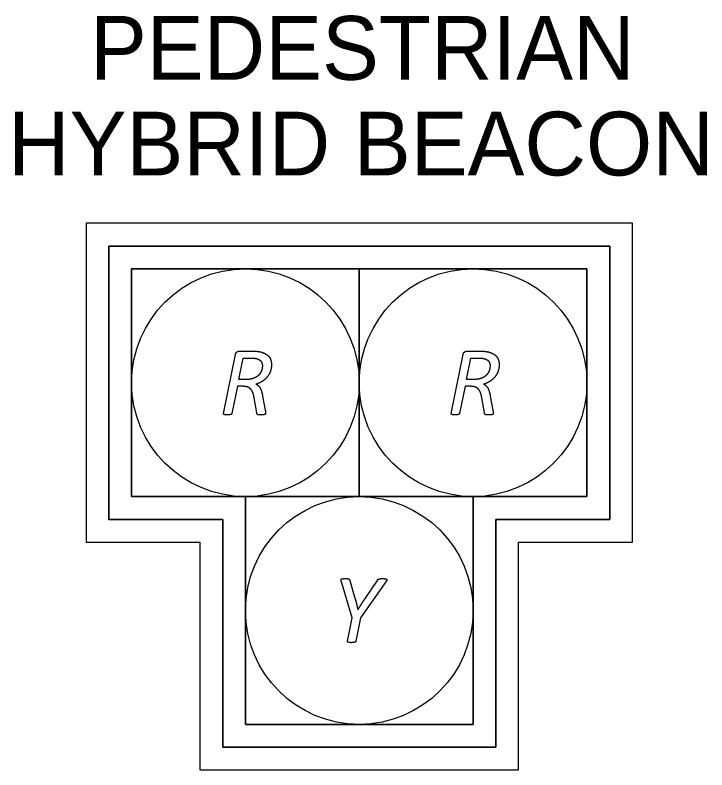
# Model space of a CAD drawing. Extents: x -30.3 to 21.6, y 6.6 to 27.2.
# Drawn here: x 16.72 to 18.239, y 9.926 to 11.583 of the extents above; entities that cross this region are included whole.
import ezdxf

# ---------------------------------------------------------------- set-up
doc = ezdxf.new("R2010")
doc.units = 0
doc.layers.add('UT_X_Water', color=7, linetype='Continuous')
doc.layers.add('VG_X_Cells', color=7, linetype='Continuous')

msp = doc.modelspace()

# ---------------------------------------------------------------- linework, layer by layer
at = {"layer": 'VG_X_Cells'}
for p, q in [((17.2127, 10.8455), (17.243, 10.8455)), ((17.2127, 10.8455), (17.243, 10.8455)), ((17.7127, 10.8455), (17.743, 10.8455)), ((17.7127, 10.8455), (17.743, 10.8455)), ((17.1778, 10.7088), (17.2037, 10.838)), ((17.1778, 10.7088), (17.2037, 10.838)), ((17.6778, 10.7088), (17.7037, 10.838)), ((17.6778, 10.7088), (17.7037, 10.838)), ((17.2631, 10.8135), (17.2631, 10.8135)), ((17.7631, 10.8135), (17.7631, 10.8135)), ((17.2506, 10.71), (17.2451, 10.7428)), ((17.2506, 10.71), (17.2451, 10.7428)), ((17.2637, 10.747), (17.2695, 10.7162)), ((17.2637, 10.747), (17.2695, 10.7162)), ((17.7506, 10.71), (17.7451, 10.7428)), ((17.7506, 10.71), (17.7451, 10.7428)), ((17.7637, 10.747), (17.7695, 10.7162)), ((17.7637, 10.747), (17.7695, 10.7162)), ((17.4553, 10.3417), (17.4664, 10.3035)), ((17.4553, 10.3417), (17.4664, 10.3035)), ((17.4893, 10.3034), (17.5156, 10.3423)), ((17.4893, 10.3034), (17.5156, 10.3423)), ((17.4728, 10.2778), (17.473, 10.2778)), ((17.4728, 10.2778), (17.473, 10.2778))]:
    msp.add_line(p, q, dxfattribs=at)
for points in [[(18.0759, 10.4262), (18.0759, 11.1262), (16.8759, 11.1262), (16.8759, 10.4262), (17.1259, 10.4262), (17.1259, 9.9262), (17.8259, 9.9262), (17.8259, 10.4262)], [(17.7759, 10.4762), (17.7759, 9.9762), (17.1759, 9.9762), (17.1759, 10.4762), (16.9259, 10.4762), (16.9259, 11.0762), (18.0259, 11.0762), (18.0259, 10.4762)], [(18.0259, 10.4762), (18.0259, 11.0762), (16.9259, 11.0762), (16.9259, 10.4762), (17.1759, 10.4762), (17.1759, 9.9762), (17.7759, 9.9762), (17.7759, 10.4762)], [(17.7259, 10.5262), (17.7259, 10.0262), (17.2259, 10.0262), (17.2259, 10.5262), (16.9759, 10.5262), (16.9759, 11.0262), (17.9759, 11.0262), (17.9759, 10.5262)], [(16.9759, 10.5262), (17.4759, 10.5262), (17.4759, 11.0262), (16.9759, 11.0262)], [(17.4759, 10.5262), (17.9759, 10.5262), (17.9759, 11.0262), (17.4759, 11.0262)], [(17.2259, 10.0262), (17.7259, 10.0262), (17.7259, 10.5262), (17.2259, 10.5262)]]:
    msp.add_lwpolyline(points, close=True, dxfattribs=at)
for points in [[(17.2276, 10.7833), (17.2113, 10.7833), (17.2207, 10.8303), (17.2399, 10.8303)], [(17.7276, 10.7833), (17.7113, 10.7833), (17.7207, 10.8303), (17.7399, 10.8303)], [(17.2206, 10.7683), (17.2082, 10.7683), (17.1963, 10.7088)], [(17.2206, 10.7683), (17.2082, 10.7683), (17.1963, 10.7088)], [(17.7206, 10.7683), (17.7082, 10.7683), (17.6963, 10.7088)], [(17.7206, 10.7683), (17.7082, 10.7683), (17.6963, 10.7088)], [(17.4501, 10.2088), (17.4604, 10.2603), (17.4366, 10.3389)], [(17.4501, 10.2088), (17.4604, 10.2603), (17.4366, 10.3389)], [(17.5341, 10.3389), (17.4789, 10.2603), (17.4687, 10.2088)], [(17.5341, 10.3389), (17.4789, 10.2603), (17.4687, 10.2088)]]:
    msp.add_lwpolyline(points, dxfattribs=at)
for centre in [(17.2259, 10.7762), (17.7259, 10.7762), (17.4759, 10.2762)]:
    msp.add_circle(centre, 0.25, dxfattribs=at)
for points in [[(17.2037, 10.838), (17.2045, 10.8422), (17.2071, 10.8438)], [(17.2037, 10.838), (17.2045, 10.8422), (17.2071, 10.8438)], [(17.2071, 10.8438), (17.2096, 10.8455), (17.2127, 10.8455)], [(17.2071, 10.8438), (17.2096, 10.8455), (17.2127, 10.8455)], [(17.243, 10.8455), (17.2529, 10.8455), (17.2604, 10.8436)], [(17.243, 10.8455), (17.2529, 10.8455), (17.2604, 10.8436)], [(17.2604, 10.8436), (17.2679, 10.8416), (17.2729, 10.8379)], [(17.2604, 10.8436), (17.2679, 10.8416), (17.2729, 10.8379)], [(17.7037, 10.838), (17.7045, 10.8422), (17.7071, 10.8438)], [(17.7037, 10.838), (17.7045, 10.8422), (17.7071, 10.8438)], [(17.7071, 10.8438), (17.7096, 10.8455), (17.7127, 10.8455)], [(17.7071, 10.8438), (17.7096, 10.8455), (17.7127, 10.8455)], [(17.743, 10.8455), (17.7529, 10.8455), (17.7604, 10.8436)], [(17.743, 10.8455), (17.7529, 10.8455), (17.7604, 10.8436)], [(17.7604, 10.8436), (17.7679, 10.8416), (17.7729, 10.8379)], [(17.7604, 10.8436), (17.7679, 10.8416), (17.7729, 10.8379)], [(17.2399, 10.8303), (17.2461, 10.8303), (17.2505, 10.8291)], [(17.2505, 10.8291), (17.255, 10.8279), (17.2578, 10.8256)], [(17.2578, 10.8256), (17.2605, 10.8234), (17.2618, 10.8202)], [(17.2729, 10.8379), (17.278, 10.8342), (17.2805, 10.8288)], [(17.2729, 10.8379), (17.278, 10.8342), (17.2805, 10.8288)], [(17.2805, 10.8288), (17.2831, 10.8233), (17.2831, 10.8163)], [(17.2805, 10.8288), (17.2831, 10.8233), (17.2831, 10.8163)], [(17.7399, 10.8303), (17.7461, 10.8303), (17.7505, 10.8291)], [(17.7505, 10.8291), (17.755, 10.8279), (17.7578, 10.8256)], [(17.7578, 10.8256), (17.7605, 10.8234), (17.7618, 10.8202)], [(17.7729, 10.8379), (17.778, 10.8342), (17.7805, 10.8288)], [(17.7729, 10.8379), (17.778, 10.8342), (17.7805, 10.8288)], [(17.7805, 10.8288), (17.7831, 10.8233), (17.7831, 10.8163)], [(17.7805, 10.8288), (17.7831, 10.8233), (17.7831, 10.8163)], [(17.2631, 10.8135), (17.2631, 10.8078), (17.2611, 10.8024)], [(17.2618, 10.8202), (17.2631, 10.8171), (17.2631, 10.8135)], [(17.2831, 10.8163), (17.2831, 10.8089), (17.281, 10.8022)], [(17.2831, 10.8163), (17.2831, 10.8089), (17.281, 10.8022)], [(17.7631, 10.8135), (17.7631, 10.8078), (17.7611, 10.8024)], [(17.7618, 10.8202), (17.7631, 10.8171), (17.7631, 10.8135)], [(17.7831, 10.8163), (17.7831, 10.8089), (17.781, 10.8022)], [(17.7831, 10.8163), (17.7831, 10.8089), (17.781, 10.8022)], [(17.2549, 10.7927), (17.2506, 10.7885), (17.2439, 10.7859)], [(17.2611, 10.8024), (17.2591, 10.797), (17.2549, 10.7927)], [(17.2746, 10.79), (17.2704, 10.7844), (17.264, 10.78)], [(17.2746, 10.79), (17.2704, 10.7844), (17.264, 10.78)], [(17.281, 10.8022), (17.2789, 10.7956), (17.2746, 10.79)], [(17.281, 10.8022), (17.2789, 10.7956), (17.2746, 10.79)], [(17.7549, 10.7927), (17.7506, 10.7885), (17.7439, 10.7859)], [(17.7611, 10.8024), (17.7591, 10.797), (17.7549, 10.7927)], [(17.7746, 10.79), (17.7704, 10.7844), (17.764, 10.78)], [(17.7746, 10.79), (17.7704, 10.7844), (17.764, 10.78)], [(17.781, 10.8022), (17.7789, 10.7956), (17.7746, 10.79)], [(17.781, 10.8022), (17.7789, 10.7956), (17.7746, 10.79)], [(17.2439, 10.7859), (17.2372, 10.7833), (17.2276, 10.7833)], [(17.264, 10.78), (17.2575, 10.7757), (17.249, 10.773)], [(17.264, 10.78), (17.2575, 10.7757), (17.249, 10.773)], [(17.249, 10.773), (17.2547, 10.7709), (17.2583, 10.7644)], [(17.249, 10.773), (17.2547, 10.7709), (17.2583, 10.7644)], [(17.7439, 10.7859), (17.7372, 10.7833), (17.7276, 10.7833)], [(17.764, 10.78), (17.7575, 10.7757), (17.749, 10.773)], [(17.764, 10.78), (17.7575, 10.7757), (17.749, 10.773)], [(17.749, 10.773), (17.7547, 10.7709), (17.7583, 10.7644)], [(17.749, 10.773), (17.7547, 10.7709), (17.7583, 10.7644)], [(17.2312, 10.7665), (17.2268, 10.7683), (17.2206, 10.7683)], [(17.2312, 10.7665), (17.2268, 10.7683), (17.2206, 10.7683)], [(17.2383, 10.7612), (17.2355, 10.7646), (17.2312, 10.7665)], [(17.2383, 10.7612), (17.2355, 10.7646), (17.2312, 10.7665)], [(17.2427, 10.7531), (17.2411, 10.7578), (17.2383, 10.7612)], [(17.2427, 10.7531), (17.2411, 10.7578), (17.2383, 10.7612)], [(17.2583, 10.7644), (17.2618, 10.7578), (17.2637, 10.747)], [(17.2583, 10.7644), (17.2618, 10.7578), (17.2637, 10.747)], [(17.7312, 10.7665), (17.7268, 10.7683), (17.7206, 10.7683)], [(17.7312, 10.7665), (17.7268, 10.7683), (17.7206, 10.7683)], [(17.7383, 10.7612), (17.7355, 10.7646), (17.7312, 10.7665)], [(17.7383, 10.7612), (17.7355, 10.7646), (17.7312, 10.7665)], [(17.7427, 10.7531), (17.7411, 10.7578), (17.7383, 10.7612)], [(17.7427, 10.7531), (17.7411, 10.7578), (17.7383, 10.7612)], [(17.7583, 10.7644), (17.7618, 10.7578), (17.7637, 10.747)], [(17.7583, 10.7644), (17.7618, 10.7578), (17.7637, 10.747)], [(17.2451, 10.7428), (17.2443, 10.7485), (17.2427, 10.7531)], [(17.2451, 10.7428), (17.2443, 10.7485), (17.2427, 10.7531)], [(17.7451, 10.7428), (17.7443, 10.7485), (17.7427, 10.7531)], [(17.7451, 10.7428), (17.7443, 10.7485), (17.7427, 10.7531)], [(17.1779, 10.7073), (17.1776, 10.708), (17.1778, 10.7088)], [(17.1779, 10.7073), (17.1776, 10.708), (17.1778, 10.7088)], [(17.1793, 10.7063), (17.1783, 10.7067), (17.1779, 10.7073)], [(17.1793, 10.7063), (17.1783, 10.7067), (17.1779, 10.7073)], [(17.182, 10.7057), (17.1802, 10.7059), (17.1793, 10.7063)], [(17.182, 10.7057), (17.1802, 10.7059), (17.1793, 10.7063)], [(17.1863, 10.7055), (17.1838, 10.7055), (17.182, 10.7057)], [(17.1863, 10.7055), (17.1838, 10.7055), (17.182, 10.7057)], [(17.1908, 10.7058), (17.189, 10.7055), (17.1863, 10.7055)], [(17.1908, 10.7058), (17.189, 10.7055), (17.1863, 10.7055)], [(17.1938, 10.7064), (17.1926, 10.706), (17.1908, 10.7058)], [(17.1938, 10.7064), (17.1926, 10.706), (17.1908, 10.7058)], [(17.1955, 10.7074), (17.195, 10.7068), (17.1938, 10.7064)], [(17.1955, 10.7074), (17.195, 10.7068), (17.1938, 10.7064)], [(17.1963, 10.7088), (17.1961, 10.7081), (17.1955, 10.7074)], [(17.1963, 10.7088), (17.1961, 10.7081), (17.1955, 10.7074)], [(17.2512, 10.7078), (17.2508, 10.7086), (17.2506, 10.71)], [(17.2512, 10.7078), (17.2508, 10.7086), (17.2506, 10.71)], [(17.2525, 10.7065), (17.2516, 10.707), (17.2512, 10.7078)], [(17.2525, 10.7065), (17.2516, 10.707), (17.2512, 10.7078)], [(17.2552, 10.7057), (17.2534, 10.7059), (17.2525, 10.7065)], [(17.2552, 10.7057), (17.2534, 10.7059), (17.2525, 10.7065)], [(17.2597, 10.7055), (17.2569, 10.7055), (17.2552, 10.7057)], [(17.2597, 10.7055), (17.2569, 10.7055), (17.2552, 10.7057)], [(17.2648, 10.7057), (17.2627, 10.7055), (17.2597, 10.7055)], [(17.2648, 10.7057), (17.2627, 10.7055), (17.2597, 10.7055)], [(17.2681, 10.7064), (17.2669, 10.7059), (17.2648, 10.7057)], [(17.2681, 10.7064), (17.2669, 10.7059), (17.2648, 10.7057)], [(17.2698, 10.7075), (17.2692, 10.7068), (17.2681, 10.7064)], [(17.2698, 10.7075), (17.2692, 10.7068), (17.2681, 10.7064)], [(17.2695, 10.7162), (17.2698, 10.7141), (17.2701, 10.7123)], [(17.2695, 10.7162), (17.2698, 10.7141), (17.2701, 10.7123)], [(17.2703, 10.7092), (17.2703, 10.7082), (17.2698, 10.7075)], [(17.2703, 10.7092), (17.2703, 10.7082), (17.2698, 10.7075)], [(17.2701, 10.7123), (17.2703, 10.7106), (17.2703, 10.7092)], [(17.2701, 10.7123), (17.2703, 10.7106), (17.2703, 10.7092)], [(17.6779, 10.7073), (17.6776, 10.708), (17.6778, 10.7088)], [(17.6779, 10.7073), (17.6776, 10.708), (17.6778, 10.7088)], [(17.6793, 10.7063), (17.6783, 10.7067), (17.6779, 10.7073)], [(17.6793, 10.7063), (17.6783, 10.7067), (17.6779, 10.7073)], [(17.682, 10.7057), (17.6802, 10.7059), (17.6793, 10.7063)], [(17.682, 10.7057), (17.6802, 10.7059), (17.6793, 10.7063)], [(17.6863, 10.7055), (17.6838, 10.7055), (17.682, 10.7057)], [(17.6863, 10.7055), (17.6838, 10.7055), (17.682, 10.7057)], [(17.6908, 10.7058), (17.689, 10.7055), (17.6863, 10.7055)], [(17.6908, 10.7058), (17.689, 10.7055), (17.6863, 10.7055)], [(17.6938, 10.7064), (17.6926, 10.706), (17.6908, 10.7058)], [(17.6938, 10.7064), (17.6926, 10.706), (17.6908, 10.7058)], [(17.6955, 10.7074), (17.695, 10.7068), (17.6938, 10.7064)], [(17.6955, 10.7074), (17.695, 10.7068), (17.6938, 10.7064)], [(17.6963, 10.7088), (17.6961, 10.7081), (17.6955, 10.7074)], [(17.6963, 10.7088), (17.6961, 10.7081), (17.6955, 10.7074)], [(17.7512, 10.7078), (17.7508, 10.7086), (17.7506, 10.71)], [(17.7512, 10.7078), (17.7508, 10.7086), (17.7506, 10.71)], [(17.7525, 10.7065), (17.7516, 10.707), (17.7512, 10.7078)], [(17.7525, 10.7065), (17.7516, 10.707), (17.7512, 10.7078)], [(17.7552, 10.7057), (17.7534, 10.7059), (17.7525, 10.7065)], [(17.7552, 10.7057), (17.7534, 10.7059), (17.7525, 10.7065)], [(17.7597, 10.7055), (17.7569, 10.7055), (17.7552, 10.7057)], [(17.7597, 10.7055), (17.7569, 10.7055), (17.7552, 10.7057)], [(17.7648, 10.7057), (17.7627, 10.7055), (17.7597, 10.7055)], [(17.7648, 10.7057), (17.7627, 10.7055), (17.7597, 10.7055)], [(17.7681, 10.7064), (17.7669, 10.7059), (17.7648, 10.7057)], [(17.7681, 10.7064), (17.7669, 10.7059), (17.7648, 10.7057)], [(17.7698, 10.7075), (17.7692, 10.7068), (17.7681, 10.7064)], [(17.7698, 10.7075), (17.7692, 10.7068), (17.7681, 10.7064)], [(17.7695, 10.7162), (17.7698, 10.7141), (17.7701, 10.7123)], [(17.7695, 10.7162), (17.7698, 10.7141), (17.7701, 10.7123)], [(17.7703, 10.7092), (17.7703, 10.7082), (17.7698, 10.7075)], [(17.7703, 10.7092), (17.7703, 10.7082), (17.7698, 10.7075)], [(17.7701, 10.7123), (17.7703, 10.7106), (17.7703, 10.7092)], [(17.7701, 10.7123), (17.7703, 10.7106), (17.7703, 10.7092)], [(17.4358, 10.3427), (17.4357, 10.3441), (17.4365, 10.3449)], [(17.4358, 10.3427), (17.4357, 10.3441), (17.4365, 10.3449)], [(17.4366, 10.3389), (17.436, 10.3413), (17.4358, 10.3427)], [(17.4366, 10.3389), (17.436, 10.3413), (17.4358, 10.3427)], [(17.4365, 10.3449), (17.4374, 10.3456), (17.4394, 10.3459)], [(17.4365, 10.3449), (17.4374, 10.3456), (17.4394, 10.3459)], [(17.4394, 10.3459), (17.4414, 10.3462), (17.4451, 10.3462)], [(17.4394, 10.3459), (17.4414, 10.3462), (17.4451, 10.3462)], [(17.4451, 10.3462), (17.4481, 10.3462), (17.4499, 10.346)], [(17.4451, 10.3462), (17.4481, 10.3462), (17.4499, 10.346)], [(17.4499, 10.346), (17.4517, 10.3458), (17.4528, 10.3453)], [(17.4499, 10.346), (17.4517, 10.3458), (17.4528, 10.3453)], [(17.4528, 10.3453), (17.4539, 10.3448), (17.4544, 10.344)], [(17.4528, 10.3453), (17.4539, 10.3448), (17.4544, 10.344)], [(17.4544, 10.344), (17.4549, 10.3431), (17.4553, 10.3417)], [(17.4544, 10.344), (17.4549, 10.3431), (17.4553, 10.3417)], [(17.5156, 10.3423), (17.5163, 10.3434), (17.5171, 10.3441)], [(17.5156, 10.3423), (17.5163, 10.3434), (17.5171, 10.3441)], [(17.5171, 10.3441), (17.5179, 10.3449), (17.5192, 10.3454)], [(17.5171, 10.3441), (17.5179, 10.3449), (17.5192, 10.3454)], [(17.5192, 10.3454), (17.5205, 10.3458), (17.5224, 10.346)], [(17.5192, 10.3454), (17.5205, 10.3458), (17.5224, 10.346)], [(17.5224, 10.346), (17.5243, 10.3462), (17.5275, 10.3462)], [(17.5224, 10.346), (17.5243, 10.3462), (17.5275, 10.3462)], [(17.5275, 10.3462), (17.5314, 10.3462), (17.5335, 10.3458)], [(17.5275, 10.3462), (17.5314, 10.3462), (17.5335, 10.3458)], [(17.5335, 10.3458), (17.5356, 10.3454), (17.5362, 10.3445)], [(17.5335, 10.3458), (17.5356, 10.3454), (17.5362, 10.3445)], [(17.5361, 10.3423), (17.5355, 10.3409), (17.5341, 10.3389)], [(17.5361, 10.3423), (17.5355, 10.3409), (17.5341, 10.3389)], [(17.5362, 10.3445), (17.5367, 10.3437), (17.5361, 10.3423)], [(17.5362, 10.3445), (17.5367, 10.3437), (17.5361, 10.3423)], [(17.4664, 10.3035), (17.4684, 10.2968), (17.4699, 10.2906)], [(17.4664, 10.3035), (17.4684, 10.2968), (17.4699, 10.2906)], [(17.4809, 10.2906), (17.4848, 10.2969), (17.4893, 10.3034)], [(17.4809, 10.2906), (17.4848, 10.2969), (17.4893, 10.3034)], [(17.4699, 10.2906), (17.4714, 10.2844), (17.4728, 10.2778)], [(17.4699, 10.2906), (17.4714, 10.2844), (17.4728, 10.2778)], [(17.473, 10.2778), (17.4769, 10.2842), (17.4809, 10.2906)], [(17.473, 10.2778), (17.4769, 10.2842), (17.4809, 10.2906)], [(17.4503, 10.2074), (17.4499, 10.2081), (17.4501, 10.2088)], [(17.4503, 10.2074), (17.4499, 10.2081), (17.4501, 10.2088)], [(17.4687, 10.2088), (17.4685, 10.2081), (17.4679, 10.2074)], [(17.4687, 10.2088), (17.4685, 10.2081), (17.4679, 10.2074)], [(17.4515, 10.2064), (17.4506, 10.2068), (17.4503, 10.2074)], [(17.4515, 10.2064), (17.4506, 10.2068), (17.4503, 10.2074)], [(17.4542, 10.2058), (17.4525, 10.206), (17.4515, 10.2064)], [(17.4542, 10.2058), (17.4525, 10.206), (17.4515, 10.2064)], [(17.4586, 10.2055), (17.4559, 10.2055), (17.4542, 10.2058)], [(17.4586, 10.2055), (17.4559, 10.2055), (17.4542, 10.2058)], [(17.463, 10.2058), (17.4612, 10.2055), (17.4586, 10.2055)], [(17.463, 10.2058), (17.4612, 10.2055), (17.4586, 10.2055)], [(17.4661, 10.2064), (17.4649, 10.206), (17.463, 10.2058)], [(17.4661, 10.2064), (17.4649, 10.206), (17.463, 10.2058)], [(17.4679, 10.2074), (17.4673, 10.2068), (17.4661, 10.2064)], [(17.4679, 10.2074), (17.4673, 10.2068), (17.4661, 10.2064)]]:
    msp.add_open_spline(points, degree=2, dxfattribs=at)

# ---------------------------------------------------------------- texts
at = {"layer": 'UT_X_Water'}
for s, p in [('PEDESTRIAN', (16.8843, 11.4413)), ('HYBRID BEACON', (16.7046, 11.2313))]:
    msp.add_text(s, height=0.14, dxfattribs=at).set_placement(p)

doc.saveas('drawing.dxf')
